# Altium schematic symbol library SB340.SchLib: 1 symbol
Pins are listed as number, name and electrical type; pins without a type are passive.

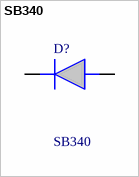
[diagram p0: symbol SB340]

## SB340
designator D?
Schottky Diodes & Rectifiers Schottky, DO-201, 40V, 3A; Manufacturer_Name: Diotec
footprint DIOAD2510W125L750D440
pins: 1 K, 2 A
